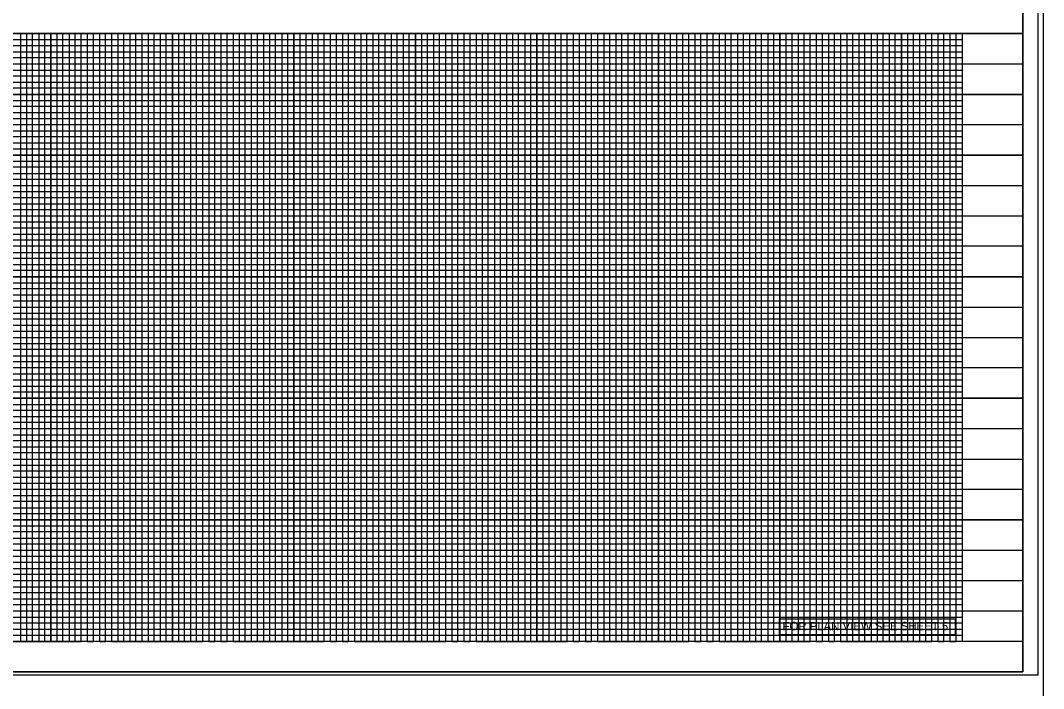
# Model space of a CAD drawing. Extents: x 1755181 to 1757273, y 729911 to 735411.
# Drawn here: x 1756023 to 1756865, y 732122 to 732672 of the extents above; entities that cross this region are included whole.
import ezdxf

# ---------------------------------------------------------------- set-up
doc = ezdxf.new("R2010")
doc.units = 0
for name, color, linetype in [('Prop Grid Mask', 7, 'Continuous'), ('Prop VPI Label', 7, 'Continuous'), ('Scratch_Level_3', 7, 'Continuous'), ('Sheet DOT Grid CELL', 7, 'Continuous'), ('Sheet Plot Border Inside CELL', 7, 'Continuous'), ('Sheet Plot Border Outside CELL', 7, 'Continuous'), ('Sheet Profile CELL', 7, 'Continuous'), ('Sheet Profile Grid Major CELL', 7, 'Continuous'), ('Sheet Profile Grid Middle CELL', 7, 'Continuous'), ('Sheet Profile Grid Minor CELL', 7, 'Continuous')]:
    doc.layers.add(name, color=color, linetype=linetype)

msp = doc.modelspace()

# ---------------------------------------------------------------- linework, layer by layer
at = {"layer": 'Prop Grid Mask'}
msp.add_lwpolyline([(1756647.46, 732179.29), (1756792.01, 732179.29), (1756792.01, 732166.28), (1756647.46, 732166.28)], close=True, dxfattribs=at)
at = {"layer": 'Scratch_Level_3'}
for points in [[(1755347.67, 732660.78), (1755347.67, 733185.78), (1756647.65, 733185.78), (1756647.63, 732952.8), (1756847.67, 732952.8), (1756847.67, 732660.78)], [(1755347.67, 732135.78), (1755347.67, 732660.78), (1756847.67, 732660.78), (1756847.67, 732135.78)]]:
    msp.add_lwpolyline(points, close=True, dxfattribs=at)
at = {"layer": 'Sheet DOT Grid CELL'}
for p, q in [((1755347.67, 732660.78), (1756847.56, 732660.78)), ((1756047.67, 732660.78), (1756047.67, 732160.78)), ((1756097.67, 732660.78), (1756097.67, 732160.78)), ((1756147.67, 732660.78), (1756147.67, 732160.78)), ((1756197.67, 732660.78), (1756197.67, 732160.78)), ((1756247.67, 732660.78), (1756247.67, 732160.78)), ((1756297.67, 732660.78), (1756297.67, 732160.78)), ((1756347.67, 732660.78), (1756347.67, 732160.78)), ((1756397.67, 732660.78), (1756397.67, 732160.78)), ((1756447.67, 732660.78), (1756447.67, 732160.78)), ((1756497.67, 732660.78), (1756497.67, 732160.78)), ((1756547.67, 732660.78), (1756547.67, 732160.78)), ((1756597.67, 732660.78), (1756597.67, 732160.78)), ((1756647.67, 732660.78), (1756647.67, 732160.78)), ((1756697.67, 732660.78), (1756697.67, 732160.78)), ((1756747.67, 732660.78), (1756747.67, 732160.78)), ((1756797.67, 732660.78), (1756797.67, 732160.78)), ((1755347.67, 732610.78), (1756847.56, 732610.78)), ((1755347.67, 732560.78), (1756847.56, 732560.78)), ((1755347.67, 732510.78), (1756847.56, 732510.78)), ((1755347.67, 732460.78), (1756847.56, 732460.78)), ((1755347.67, 732410.78), (1756847.56, 732410.78)), ((1755347.67, 732360.78), (1756847.56, 732360.78)), ((1755347.67, 732310.78), (1756847.56, 732310.78)), ((1755347.67, 732260.78), (1756847.56, 732260.78)), ((1755347.67, 732210.78), (1756847.56, 732210.78))]:
    msp.add_line(p, q, dxfattribs=at)
at = {"layer": 'Sheet Plot Border Inside CELL'}
msp.add_lwpolyline([(1755193.67, 732133.23), (1756860.17, 732133.23), (1756860.17, 733188.33), (1755193.67, 733188.33)], close=True, dxfattribs=at)
at = {"layer": 'Sheet Plot Border Outside CELL'}
msp.add_lwpolyline([(1755180.67, 732110.78), (1756864.67, 732110.78), (1756864.67, 733210.78), (1755180.67, 733210.78)], close=True, dxfattribs=at)
at = {"layer": 'Sheet Profile CELL'}
for p, q in [((1755347.67, 732660.78), (1756847.67, 732660.78)), ((1756847.67, 732160.78), (1755347.67, 732160.78)), ((1755347.67, 732135.78), (1756847.67, 732135.78))]:
    msp.add_line(p, q, dxfattribs=at)
msp.add_lwpolyline([(1756847.67, 733185.78), (1755347.67, 733185.78), (1755347.67, 732135.78), (1756847.67, 732135.78)], close=True, dxfattribs=at)
at = {"layer": 'Sheet Profile Grid Major CELL'}
for p, q in [((1756047.67, 732660.78), (1756097.67, 732660.78)), ((1756147.67, 732660.78), (1756197.67, 732660.78)), ((1756247.67, 732660.78), (1756297.67, 732660.78)), ((1756347.67, 732660.78), (1756397.67, 732660.78)), ((1756447.67, 732660.78), (1756497.67, 732660.78)), ((1756547.67, 732660.78), (1756597.67, 732660.78)), ((1756647.67, 732660.78), (1756697.67, 732660.78)), ((1756747.67, 732660.78), (1756797.67, 732660.78)), ((1756747.67, 732160.78), (1756747.67, 732160.78))]:
    msp.add_line(p, q, dxfattribs=at)
for points in [[(1755997.67, 732160.78), (1756047.67, 732160.78), (1756047.67, 732660.78), (1756097.67, 732660.78), (1756097.67, 732160.78), (1756147.67, 732160.78), (1756147.67, 732660.78), (1756197.67, 732660.78), (1756197.67, 732160.78), (1756247.67, 732160.78), (1756247.67, 732660.78), (1756297.67, 732660.78), (1756297.67, 732160.78), (1756347.67, 732160.78), (1756347.67, 732660.78), (1756397.67, 732660.78), (1756397.67, 732160.78), (1756447.67, 732160.78), (1756447.67, 732660.78), (1756497.67, 732660.78), (1756497.67, 732160.78), (1756547.67, 732160.78), (1756547.67, 732660.78), (1756597.67, 732660.78), (1756597.67, 732160.78), (1756647.67, 732160.78), (1756647.67, 732660.78), (1756697.67, 732660.78), (1756697.67, 732160.78), (1756747.67, 732160.78), (1756747.67, 732160.78), (1756747.67, 732660.78), (1756797.67, 732660.78), (1756797.67, 732160.78)], [(1756847.67, 732610.78), (1755347.67, 732610.78)], [(1756847.67, 732560.78), (1755347.67, 732560.78), (1755347.67, 732510.78), (1756847.67, 732510.78)], [(1756847.67, 732460.78), (1755347.67, 732460.78), (1755347.67, 732410.78), (1756847.67, 732410.78)], [(1756847.67, 732360.78), (1755347.67, 732360.78), (1755347.67, 732310.78), (1756847.67, 732310.78)], [(1756847.67, 732260.78), (1755347.67, 732260.78), (1755347.67, 732260.78), (1755347.67, 732210.78), (1756847.67, 732210.78)], [(1756847.67, 732160.78), (1755347.67, 732160.78)]]:
    msp.add_lwpolyline(points, dxfattribs=at)
at = {"layer": 'Sheet Profile Grid Middle CELL'}
for points in [[(1755972.67, 732660.78), (1756022.67, 732660.78), (1756022.67, 732160.78), (1756072.67, 732160.78), (1756072.67, 732660.78), (1756122.67, 732660.78), (1756122.67, 732160.78), (1756172.67, 732160.78), (1756172.67, 732660.78), (1756222.67, 732660.78), (1756222.67, 732160.78), (1756272.67, 732160.78), (1756272.67, 732660.78), (1756322.67, 732660.78), (1756322.67, 732160.78), (1756372.67, 732160.78), (1756372.67, 732660.78), (1756422.67, 732660.78), (1756422.67, 732160.78), (1756472.67, 732160.78), (1756472.67, 732660.78), (1756522.67, 732660.78), (1756522.67, 732160.78), (1756572.67, 732160.78), (1756572.67, 732660.78), (1756622.67, 732660.78), (1756622.67, 732160.78), (1756672.67, 732160.78), (1756672.67, 732660.78), (1756722.67, 732660.78), (1756722.67, 732160.78), (1756772.67, 732160.78), (1756772.67, 732660.78)], [(1755347.67, 732635.78), (1756847.67, 732635.78)], [(1756847.67, 732585.78), (1755347.67, 732585.78), (1755347.67, 732535.78), (1756847.67, 732535.78)], [(1756847.67, 732485.78), (1755347.67, 732485.78), (1755347.67, 732435.78), (1756847.67, 732435.78)], [(1756847.67, 732385.78), (1755347.67, 732385.78), (1755347.67, 732335.78), (1756847.67, 732335.78)], [(1756847.67, 732285.78), (1755347.67, 732285.78), (1755347.67, 732235.78), (1756847.67, 732235.78)], [(1756847.67, 732185.78), (1755347.67, 732185.78)]]:
    msp.add_lwpolyline(points, dxfattribs=at)
at = {"layer": 'Sheet Profile Grid Minor CELL'}
for p, q in [((1755397.67, 732655.78), (1756797.67, 732655.78)), ((1756797.67, 732650.78), (1755397.67, 732650.78)), ((1755397.67, 732645.78), (1756797.67, 732645.78)), ((1756797.67, 732640.78), (1755397.67, 732640.78)), ((1755397.67, 732630.78), (1756797.67, 732630.78)), ((1756797.67, 732625.78), (1755397.67, 732625.78)), ((1755397.67, 732620.78), (1756797.67, 732620.78)), ((1756797.67, 732615.78), (1755397.67, 732615.78)), ((1755397.67, 732605.78), (1756797.67, 732605.78)), ((1756797.67, 732600.78), (1755397.67, 732600.78)), ((1755397.67, 732595.78), (1756797.67, 732595.78)), ((1756797.67, 732590.78), (1755397.67, 732590.78)), ((1755397.67, 732580.78), (1756797.67, 732580.78)), ((1756797.67, 732575.78), (1755397.67, 732575.78)), ((1755397.67, 732570.78), (1756797.67, 732570.78)), ((1756797.67, 732565.78), (1755397.67, 732565.78)), ((1755397.67, 732555.78), (1756797.67, 732555.78)), ((1756797.67, 732550.78), (1755397.67, 732550.78)), ((1755397.67, 732545.78), (1756797.67, 732545.78)), ((1756797.67, 732540.78), (1755397.67, 732540.78)), ((1755397.67, 732530.78), (1756797.67, 732530.78)), ((1756797.67, 732525.78), (1755397.67, 732525.78)), ((1755397.67, 732520.78), (1756797.67, 732520.78)), ((1756797.67, 732515.78), (1755397.67, 732515.78)), ((1755397.67, 732505.78), (1756797.67, 732505.78)), ((1756797.67, 732500.78), (1755397.67, 732500.78)), ((1755397.67, 732495.78), (1756797.67, 732495.78)), ((1756797.67, 732490.78), (1755397.67, 732490.78)), ((1755397.67, 732480.78), (1756797.67, 732480.78)), ((1756797.67, 732475.78), (1755397.67, 732475.78)), ((1755397.67, 732470.78), (1756797.67, 732470.78)), ((1756797.67, 732465.78), (1755397.67, 732465.93)), ((1755397.67, 732455.78), (1756797.67, 732455.78)), ((1756797.67, 732450.78), (1755397.67, 732450.78)), ((1755397.67, 732445.78), (1756797.67, 732445.78)), ((1756797.67, 732440.78), (1755397.67, 732440.78)), ((1755397.67, 732430.78), (1756797.67, 732430.78)), ((1756797.67, 732425.78), (1755397.67, 732425.78)), ((1755397.67, 732420.78), (1756797.67, 732420.78)), ((1756797.67, 732415.78), (1755397.67, 732415.78)), ((1755397.67, 732405.78), (1756797.67, 732405.78)), ((1756797.67, 732400.78), (1755397.67, 732400.78)), ((1755397.67, 732395.78), (1756797.67, 732395.78)), ((1756797.67, 732390.78), (1755397.67, 732390.78)), ((1755397.67, 732380.78), (1756797.67, 732380.78)), ((1756797.67, 732375.78), (1755397.67, 732375.78)), ((1755397.67, 732370.78), (1756797.67, 732370.78)), ((1756797.67, 732365.78), (1755397.67, 732365.78)), ((1755397.67, 732355.78), (1756797.67, 732355.78)), ((1756797.67, 732350.78), (1755397.67, 732350.78)), ((1755397.67, 732345.78), (1756797.67, 732345.78)), ((1756797.67, 732340.78), (1755397.67, 732340.78)), ((1755397.67, 732330.78), (1756797.67, 732330.78)), ((1756797.67, 732325.78), (1755397.67, 732325.78)), ((1755397.67, 732320.78), (1756797.67, 732320.78)), ((1756797.67, 732315.78), (1755397.67, 732315.78)), ((1755397.67, 732305.78), (1756797.67, 732305.78)), ((1756797.67, 732300.78), (1755397.67, 732300.78)), ((1755397.67, 732295.78), (1756797.67, 732295.78)), ((1756797.67, 732290.78), (1755397.67, 732290.78)), ((1755397.67, 732280.78), (1756797.67, 732280.78)), ((1756797.67, 732275.78), (1755397.67, 732275.78)), ((1755397.67, 732270.78), (1756797.67, 732270.78)), ((1756797.67, 732265.78), (1755397.67, 732265.78)), ((1755397.67, 732255.78), (1756797.67, 732255.78)), ((1756797.67, 732250.78), (1755397.67, 732250.78)), ((1755397.67, 732245.78), (1756797.67, 732245.78)), ((1756797.67, 732240.78), (1755397.67, 732240.78)), ((1755397.67, 732230.78), (1756797.67, 732230.78)), ((1756797.67, 732225.78), (1755397.67, 732225.78)), ((1755397.67, 732220.78), (1756797.67, 732220.78)), ((1756797.67, 732215.78), (1755397.67, 732215.78)), ((1755397.67, 732205.78), (1756797.67, 732205.78)), ((1756797.67, 732200.78), (1755397.67, 732200.78)), ((1755397.67, 732195.78), (1756797.67, 732195.78)), ((1756797.67, 732190.78), (1755397.67, 732190.78)), ((1755397.67, 732180.78), (1756797.67, 732180.78)), ((1756797.67, 732175.78), (1755397.67, 732175.78)), ((1755397.67, 732170.78), (1756797.67, 732170.78)), ((1755397.67, 732165.78), (1756797.67, 732165.78)), ((1756797.67, 732165.78), (1756797.67, 732165.78))]:
    msp.add_line(p, q, dxfattribs=at)
for points in [[(1756017.67, 732660.78), (1756027.67, 732660.78), (1756027.67, 732160.78), (1756032.67, 732160.78), (1756032.67, 732660.78), (1756037.67, 732660.78), (1756037.67, 732160.78), (1756042.67, 732160.78), (1756042.67, 732660.78), (1756052.67, 732660.78), (1756052.67, 732160.78), (1756052.67, 732160.78), (1756057.67, 732160.78), (1756057.67, 732660.78), (1756062.67, 732660.78), (1756062.67, 732160.78), (1756067.67, 732160.78), (1756067.67, 732660.78), (1756077.67, 732660.78), (1756077.67, 732160.78), (1756082.67, 732160.78), (1756082.67, 732660.78), (1756087.67, 732660.78), (1756087.67, 732160.78), (1756092.67, 732160.78), (1756092.67, 732660.78), (1756102.67, 732660.78), (1756102.67, 732160.78), (1756107.67, 732160.78), (1756107.67, 732660.78), (1756112.67, 732660.78), (1756112.67, 732160.78), (1756117.67, 732160.78), (1756117.67, 732660.78), (1756127.67, 732660.78), (1756127.67, 732160.78), (1756132.67, 732160.78), (1756132.67, 732660.78), (1756137.67, 732660.78), (1756137.67, 732160.78), (1756142.67, 732160.78), (1756142.67, 732660.78), (1756152.67, 732660.78), (1756152.67, 732160.78), (1756157.67, 732160.78), (1756157.67, 732660.78), (1756162.67, 732660.78), (1756162.67, 732160.78), (1756167.67, 732160.78), (1756167.67, 732660.78), (1756177.67, 732660.78), (1756177.67, 732160.78), (1756182.67, 732160.78), (1756182.67, 732660.78), (1756187.67, 732660.78), (1756187.67, 732160.78), (1756192.67, 732160.78), (1756192.67, 732660.78), (1756202.67, 732660.78), (1756202.67, 732160.78), (1756207.37, 732161.33), (1756207.67, 732160.78), (1756207.67, 732660.78), (1756212.67, 732660.78), (1756212.67, 732160.78), (1756217.67, 732160.78), (1756217.67, 732660.78), (1756227.67, 732660.78), (1756227.67, 732160.78), (1756232.67, 732160.78)], [(1756232.67, 732160.78), (1756232.67, 732660.78), (1756237.67, 732660.78), (1756237.67, 732160.78), (1756242.67, 732160.78), (1756242.67, 732660.78), (1756252.67, 732660.78), (1756252.67, 732160.78), (1756257.67, 732160.78), (1756257.67, 732660.78), (1756262.67, 732660.78), (1756262.67, 732160.78), (1756267.67, 732160.78), (1756267.67, 732660.78), (1756277.67, 732660.78), (1756277.67, 732160.78), (1756282.67, 732160.78), (1756282.67, 732660.78), (1756287.67, 732660.78), (1756287.67, 732160.78), (1756292.67, 732160.78), (1756292.67, 732660.78), (1756302.67, 732660.78), (1756302.67, 732160.78), (1756307.67, 732160.78), (1756307.67, 732660.78), (1756312.67, 732660.78), (1756312.67, 732160.78), (1756317.67, 732160.78), (1756317.67, 732660.78), (1756327.67, 732660.78), (1756327.67, 732160.78), (1756332.67, 732160.78), (1756332.67, 732660.78), (1756337.67, 732660.78), (1756337.67, 732160.78), (1756342.67, 732160.78), (1756342.67, 732660.78), (1756352.67, 732660.78), (1756352.67, 732160.78), (1756357.67, 732160.78), (1756357.67, 732660.78), (1756362.67, 732660.78), (1756362.67, 732160.78), (1756367.67, 732160.78), (1756367.67, 732660.78), (1756377.67, 732660.78), (1756377.67, 732160.78), (1756382.67, 732160.78), (1756382.67, 732660.78), (1756387.67, 732660.78), (1756387.67, 732160.78), (1756392.67, 732160.78), (1756392.67, 732660.78), (1756402.67, 732660.78), (1756402.67, 732160.78), (1756407.67, 732160.78), (1756407.67, 732660.78), (1756412.67, 732660.78), (1756412.67, 732160.78), (1756417.67, 732160.78), (1756417.67, 732660.78), (1756427.67, 732660.78), (1756427.67, 732160.78), (1756432.67, 732160.78), (1756432.67, 732660.78), (1756437.67, 732660.78), (1756437.67, 732160.78), (1756442.67, 732160.78), (1756442.67, 732660.78), (1756452.67, 732660.78), (1756452.67, 732160.78), (1756457.67, 732160.78), (1756457.67, 732660.78), (1756462.67, 732660.78), (1756462.67, 732160.78), (1756467.67, 732160.78), (1756467.67, 732660.78), (1756477.67, 732660.78), (1756477.67, 732160.78), (1756482.67, 732160.78), (1756482.67, 732660.78), (1756487.67, 732660.78), (1756487.67, 732160.78), (1756492.67, 732160.78), (1756492.67, 732660.78), (1756502.67, 732660.78), (1756502.67, 732160.78), (1756507.67, 732160.78), (1756507.67, 732660.78), (1756512.67, 732660.78), (1756512.67, 732160.78), (1756517.67, 732160.78), (1756517.67, 732660.78), (1756527.67, 732660.78), (1756527.67, 732160.78), (1756532.67, 732160.78), (1756532.67, 732660.78), (1756537.67, 732660.78), (1756537.67, 732160.78)], [(1756537.67, 732160.78), (1756542.67, 732160.78), (1756542.67, 732660.78), (1756552.67, 732660.78), (1756552.67, 732160.78), (1756557.67, 732160.78), (1756557.67, 732660.78), (1756562.67, 732660.78), (1756562.67, 732160.78), (1756567.67, 732160.78), (1756567.67, 732660.78), (1756577.67, 732660.78), (1756577.67, 732160.78), (1756582.67, 732160.78), (1756582.67, 732660.78), (1756587.67, 732660.78), (1756587.67, 732160.78), (1756592.67, 732160.78), (1756592.67, 732660.78), (1756602.67, 732660.78), (1756602.67, 732160.78), (1756607.67, 732160.78), (1756607.67, 732660.78), (1756612.67, 732660.78), (1756612.67, 732160.78), (1756617.67, 732160.78), (1756617.67, 732660.78), (1756627.67, 732660.78), (1756627.67, 732160.78), (1756632.67, 732160.78), (1756632.67, 732660.78), (1756637.67, 732660.78), (1756637.67, 732160.78), (1756642.67, 732160.78), (1756642.67, 732660.78), (1756652.67, 732660.78), (1756652.67, 732160.78), (1756657.67, 732160.78), (1756657.67, 732660.78), (1756662.67, 732660.78), (1756662.67, 732160.78), (1756667.67, 732160.78), (1756667.67, 732660.78), (1756677.67, 732660.78), (1756677.67, 732160.78), (1756682.67, 732160.78), (1756682.67, 732660.78), (1756687.67, 732660.78), (1756687.67, 732160.78), (1756692.67, 732160.78), (1756692.67, 732660.78), (1756702.67, 732660.78), (1756702.67, 732160.78), (1756707.67, 732160.78), (1756707.67, 732660.78), (1756712.67, 732660.78), (1756712.67, 732160.78), (1756717.67, 732160.78), (1756717.67, 732660.78), (1756727.67, 732660.78), (1756727.67, 732160.78), (1756732.67, 732160.78), (1756732.67, 732660.78), (1756737.67, 732660.78), (1756737.67, 732160.78), (1756742.67, 732160.78), (1756742.67, 732660.78), (1756752.67, 732660.78), (1756752.67, 732160.78), (1756757.67, 732160.78), (1756757.67, 732660.78), (1756762.67, 732660.78), (1756762.67, 732160.78), (1756767.67, 732160.78), (1756767.67, 732660.78), (1756777.67, 732660.78), (1756777.67, 732160.78), (1756782.67, 732160.78), (1756782.67, 732660.78), (1756787.67, 732660.78), (1756787.67, 732160.78), (1756792.67, 732160.78), (1756792.67, 732660.78), (1756797.67, 732660.78)]]:
    msp.add_lwpolyline(points, dxfattribs=at)

# ---------------------------------------------------------------- texts
at = {"layer": 'Prop VPI Label'}
msp.add_text('FOR PLAN VIEW SEE SHEET 5', height=7, dxfattribs=at).set_placement((1756649.85, 732169.86))

doc.saveas('drawing.dxf')
